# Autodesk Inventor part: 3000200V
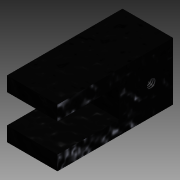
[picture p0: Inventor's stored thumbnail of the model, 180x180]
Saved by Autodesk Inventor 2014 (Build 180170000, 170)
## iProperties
Company: NHTSA/VRTC
Created: 2012-11
Material: Generic
Document SubType Name: Modeling
Designer: Mike Vanvoorhis
Density: 1 g/cm^3
Project: CHILD SIDE IMPACT SLED
Description: LIGHT TRAP SENSOR
Catalog Web Link: www.ghisys.com/
Vendor: GHI Systems, Inc.
Stock Number: VSDI
Part Number: 3000200V
Appearance: Black
Author: Dave Walker
Title: Light trap Sensor
Subject: Child Side Impact Sled
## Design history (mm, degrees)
sketch "Sketch1"
  geometry: L1 (0, 0)-(0, 101.6); L2 (0, 0)-(50.8, 0); L3 (50.8, 0)-(50.8, 101.6); L4 (50.8, 101.6)-(38.1, 101.6); L5 (38.1, 101.6)-(38.1, 47.625); L6 (38.1, 47.625)-(12.7, 47.625); L7 (0, 101.6)-(12.7, 101.6); L8 (12.7, 101.6)-(12.7, 47.625); L9 (25.4, 0)-(25.4, 19.05); C1 r 4.763 at (25.4, 19.05)
  constraints: 18 end point, 4 perpendicular, 3 parallel, 1 centre point, 1 coincident, 1 midpoint, 1 vertical
  dimensions: "d0" = 101.6 distance of L1.start L1.end; "d1" = 50.8 distance of L1.start L2.end; "d2" = 101.6 distance of L2.end L3.end; "d4" = 12.7 distance of L3.end L4.end; "d5" = 53.975 distance of L4.end L5.end; "d6" = 25.4 distance of L5.end L6.end; "d7" = 12.7 distance of L1.end L7.end; "d10" = 19.05 distance of L9.start L9.end; "d11" = 9.525 diameter of C1
extrude "Extrusion1" new body sketch "Sketch1" distance "d8" = 44.45; taper "d9" = 0 deg
sketch "Sketch2"
  geometry: L1 (0, 50.8)-(0, 0) reference; L2 (-101.6, 0)-(-101.6, 12.7) reference; L3 (0, 25.4)-(-19.05, 25.4)
  constraints: 2 end point, 1 midpoint, 1 perpendicular
  dimensions: "d12" = 19.05 distance of L3.start L3.end
hole "Hole1" sketch "Sketch2" at (-19.05, 25.4) diameter "d13" = 7.7978; stored, may be unused: countersink angle "d17" = 82 deg, drill point angle "d19" = 118 deg; dims "d14" = 19.05, "d15" = 9.525, "d16" = 6.35, "d18" = 12.7
body "Solid1"
